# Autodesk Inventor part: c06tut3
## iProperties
Shininess: 77.0
Length Units: 11269
Angle Units: 11279
Time Units: 11290
Mass Units: 11283
Length Display Precision: 3
Angle Display Precision: 2
Created: 2001-12
Part Number: c06tut3
Document SubType Name: Modeling
Designer: Renu Muthoo
Density: 0.0
Volumn: 0.0
Area: 0.0
PropertySet Name: Model Information
Control State: 0
Master: False
Checked Out: False
Author: Renu Muthoo
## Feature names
1. Extrusion1
2. Extrusion2
3. Extrusion3
4. Hole1
5. Hole2
6. Circular Pattern1
7. Extrusion4
8. Circular Pattern2
9. Mirror1
